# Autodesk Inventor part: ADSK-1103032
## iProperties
Shininess: 41.0
Length Units: 11272
Angle Units: 11279
Time Units: 11290
Mass Units: 11286
Length Display Precision: 4
Angle Display Precision: 2
Compacted: True
Created: 2000-08
Part Number: ADSK-1103032
Document SubType Name: Modeling
Description: CLUTCH SHOE
Mass: 0.774234 g
Surface Area: 2.85495 cm^2
Volume: 0.171671 cm^3
Density: 4.51 g/cm^3
Material: Titanium
Density: 0.0
Volumn: 0.0
Area: 0.0
PropertySet Name: Model Information
Control State: 0
Master: False
Checked Out: False
Author: Autodesk, Inc.
